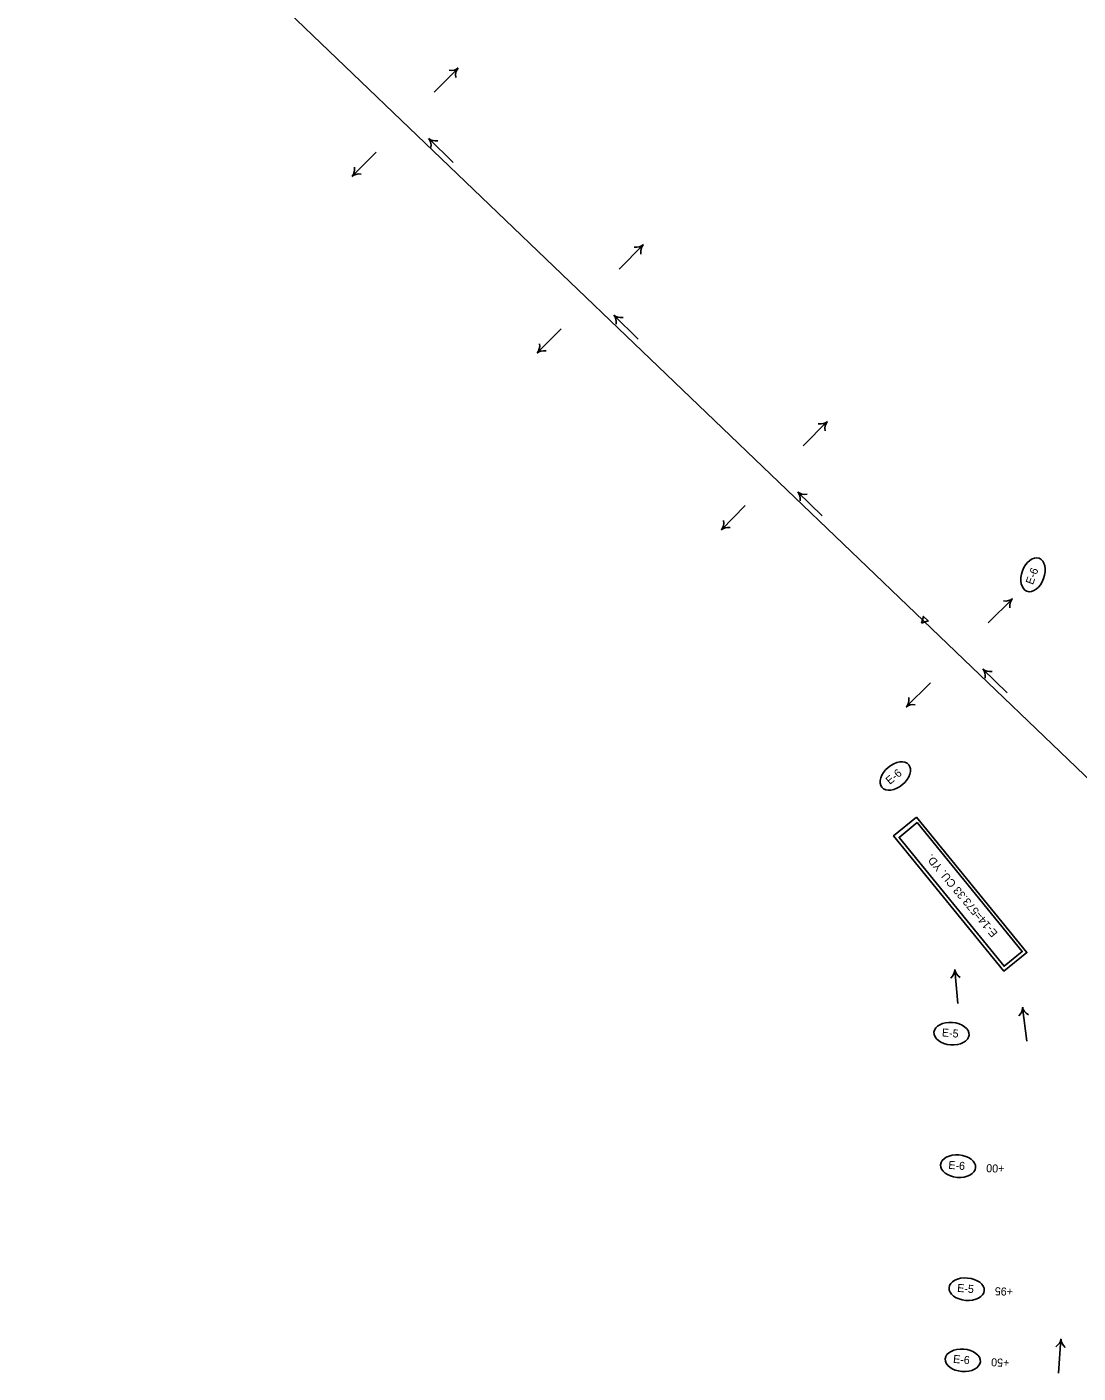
# Model space of a CAD drawing. Extents: x 669236 to 673912, y 735758 to 754788.
# Drawn here: x 670712 to 671532, y 752616 to 753668 of the extents above; entities that cross this region are included whole.
import ezdxf

# ---------------------------------------------------------------- set-up
doc = ezdxf.new("R2010")
doc.units = 0
for name, color, linetype in [('Default', 7, 'Continuous'), ('Prop_Horiz Alignment', 7, 'Continuous'), ('R_Erosion_3', 7, 'Continuous'), ('R_Flow Arrows', 7, 'Continuous')]:
    doc.layers.add(name, color=color, linetype=linetype)

msp = doc.modelspace()

# ---------------------------------------------------------------- linework, layer by layer
at = {"layer": 'Default'}
for p, q in [((671411.7, 753203.9), (670711.7, 753875.4)), ((671992.6, 752646.7), (671411.7, 753203.9))]:
    msp.add_line(p, q, dxfattribs=at)
at = {"layer": 'Prop_Horiz Alignment'}
msp.add_lwpolyline([(671410, 753202.1), (671411.7, 753207.4), (671415.3, 753204)], close=True, dxfattribs=at)
at = {"layer": 'R_Erosion_3'}
for points in [[(671406.1, 753050.7), (671492.3, 752944.9), (671474.4, 752930.3), (671388.2, 753036.1)], [(671406.7, 753046.4), (671488.7, 752945.7), (671474.5, 752934.2), (671392.6, 753034.8)]]:
    msp.add_lwpolyline(points, close=True, dxfattribs=at)
for centre, major_axis in [((671497.1, 753240), (4.7, 12.9)), ((671389.6, 753082.8), (10.5, 8.8)), ((671433.5, 752881.6), (13.7, -1.1)), ((671438.6, 752778.1), (13.7, -1.1)), ((671445.3, 752682), (13.7, -1.1)), ((671442.3, 752626.5), (13.7, -1.1))]:
    msp.add_ellipse(centre, major_axis=major_axis, ratio=0.638788, dxfattribs=at)
at = {"layer": 'R_Flow Arrows'}
for p, q in [((671048.3, 753635.6), (671029.5, 753616.8)), ((671025.4, 753580.7), (671044.3, 753562.1)), ((670965.6, 753551.2), (670984.3, 753570)), ((671192.8, 753497.6), (671174, 753478.8)), ((671169.9, 753442.7), (671188.8, 753424.1)), ((671110.1, 753413.2), (671128.8, 753432)), ((671336.5, 753359.6), (671317.7, 753340.8)), ((671313.6, 753304.6), (671332.5, 753286)), ((671253.8, 753275.2), (671272.5, 753294)), ((671481, 753221.2), (671462.2, 753202.4)), ((671458, 753166.3), (671477, 753147.7)), ((671398.2, 753136.8), (671417, 753155.6)), ((671436.1, 752931.5), (671438.5, 752905.1)), ((671489, 752902.1), (671492.3, 752875.8)), ((671518.9, 752643), (671517.1, 752616.5))]:
    msp.add_line(p, q, dxfattribs=at)
for centre, major_axis, start_param, end_param in [((671034.3, 753650.2), (14.3, -14.2), 5.662936, 6.259934), ((671062.7, 753621.6), (-14.3, 14.2), 0.023252, 0.620249), ((671010.9, 753566.6), (14.1, 14.4), 5.662936, 6.259934), ((671039.3, 753595.3), (-14.1, -14.4), 0.023252, 0.620249), ((670951.1, 753565.3), (14.3, -14.2), 0.023252, 0.620249), ((670979.5, 753536.7), (-14.3, 14.2), 5.662936, 6.259934), ((671178.8, 753512.2), (14.3, -14.2), 5.662936, 6.259934), ((671207.3, 753483.6), (-14.3, 14.2), 0.023252, 0.620249), ((671155.5, 753428.6), (14.1, 14.4), 5.662936, 6.259934), ((671183.8, 753457.3), (-14.1, -14.4), 0.023252, 0.620249), ((671095.6, 753427.3), (14.3, -14.2), 0.023252, 0.620249), ((671124, 753398.7), (-14.3, 14.2), 5.662936, 6.259934), ((671322.5, 753374.1), (14.3, -14.2), 5.662936, 6.259934), ((671351, 753345.5), (-14.3, 14.2), 0.023252, 0.620249), ((671299.1, 753290.6), (14.1, 14.4), 5.662936, 6.259934), ((671327.5, 753319.2), (-14.1, -14.4), 0.023252, 0.620249), ((671239.3, 753289.2), (14.3, -14.2), 0.023252, 0.620249), ((671267.7, 753260.6), (-14.3, 14.2), 5.662936, 6.259934), ((671467, 753235.8), (14.3, -14.2), 5.662936, 6.259934), ((671495.4, 753207.2), (-14.3, 14.2), 0.023252, 0.620249), ((671443.6, 753152.2), (14.1, 14.4), 5.662936, 6.259934), ((671472, 753180.8), (-14.1, -14.4), 0.023252, 0.620249), ((671412.2, 753122.3), (-14.3, 14.2), 5.662936, 6.259934), ((671383.8, 753150.9), (14.3, -14.2), 0.023252, 0.620249), ((671415.9, 752930.1), (20.1, 1.8), 5.662936, 6.259934), ((671456.1, 752933.6), (-20.1, -1.8), 0.023252, 0.620249), ((671469, 752900.1), (20, 2.5), 5.662936, 6.259934), ((671509, 752904.8), (-20, -2.5), 0.023252, 0.620249), ((671498.9, 752644.8), (20.1, -1.4), 5.662936, 6.259934), ((671539.1, 752641.9), (-20.1, 1.4), 0.023252, 0.620249)]:
    msp.add_ellipse(centre, major_axis=major_axis, ratio=0.5625, start_param=start_param, end_param=end_param, dxfattribs=at)

# ---------------------------------------------------------------- texts
at = {"layer": 'R_Erosion_3'}
for s, rotation, p in [('E-6', 69.7849, (671497, 753231.8)), ('E-6', 39.7214, (671385.3, 753075.8)), ('E-14=573.33 CU. YD.', 129.9127, (671469.9, 752960.2)), ('E-5', 355.2534, (671425.8, 752879.5)), ('E-6', 355.2534, (671430.8, 752776.1)), ('+00', 177.4275, (671474.9, 752779.1)), ('E-5', 355.2534, (671437.7, 752680)), ('+95', 177.4275, (671481.6, 752683)), ('E-6', 355.2534, (671434.5, 752624.5)), ('+50', 177.4275, (671478.7, 752627.5))]:
    msp.add_text(s, height=6.25, rotation=rotation, dxfattribs=at).set_placement(p)

doc.saveas('drawing.dxf')
